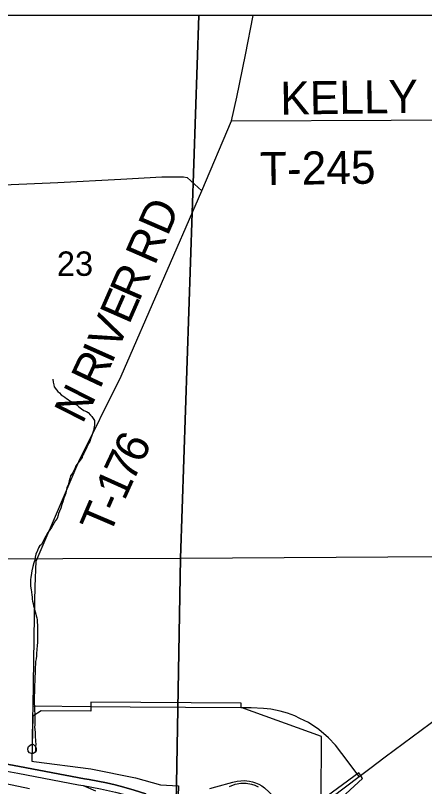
# Model space of a CAD drawing. Extents: x -8.5 to 18.7, y -20.3 to 7.
# Drawn here: x -2.768 to -1.362, y 4.29 to 6.938 of the extents above; entities that cross this region are included whole.
import ezdxf

# ---------------------------------------------------------------- set-up
doc = ezdxf.new("R2010")
doc.units = 0
for name, color, linetype in [('Default', 7, 'Continuous'), ('GM_X_City_Street', 7, 'Continuous'), ('GM_X_Corporation', 7, 'Continuous'), ('GM_X_Interchange_Ramps', 7, 'Continuous'), ('GM_X_Minor_River', 7, 'Continuous'), ('GM_X_Section', 7, 'Continuous'), ('GM_X_Section_Text', 7, 'Continuous'), ('GM_X_State_Route', 7, 'Continuous'), ('GM_X_Township_Road', 7, 'Continuous'), ('GM_X_Township_Road_Text', 7, 'Continuous'), ('GM_X_US_Route', 7, 'Continuous'), ('SH_Cut_Line', 7, 'Continuous')]:
    doc.layers.add(name, color=color, linetype=linetype)

msp = doc.modelspace()

# ---------------------------------------------------------------- linework, layer by layer
at = {"layer": 'Default'}
msp.add_lwpolyline([(-3.0114, 5.0714), (-2.2011, 5.074), (-2.1387, 6.938), (-3.0796, 6.938)], dxfattribs=at)
msp.add_lwpolyline([(-0.1988, 6.938), (-2.1387, 6.938), (-2.2011, 5.074), (-0.2415, 5.0861)], close=True, dxfattribs=at)
at = {"layer": 'GM_X_City_Street'}
for points in [[(-1.9484, 3.9747), (-1.5754, 4.3178), (-1.5825, 4.329), (-1.5882, 4.3371), (-1.7175, 4.2414), (-1.7163, 4.462), (-1.9932, 4.561), (-1.9925, 4.5756), (-2.5089, 4.5796), (-2.5097, 4.5648), (-2.5097, 4.5484), (-2.6796, 4.5501), (-2.7088, 4.5316), (-2.7117, 4.3765), (-2.7049, 4.3756), (-2.5096, 4.3502), (-2.3562, 4.3194), (-2.2694, 4.2958), (-2.2079, 4.2918), (-2.2137, 4.1138)], [(-2.7206, 4.2815), (-3.5022, 4.4472), (-3.5552, 4.4573), (-3.6617, 4.2047)]]:
    msp.add_lwpolyline(points, dxfattribs=at)
at = {"layer": 'GM_X_Corporation'}
msp.add_lwpolyline([(-0.1911, 6.938), (-8.4587, 6.938), (-8.4587, 1.1732)], dxfattribs=at)
at = {"layer": 'GM_X_Interchange_Ramps'}
msp.add_lwpolyline([(-2.0322, 4.2895), (-2.0133, 4.2976), (-1.9941, 4.301), (-1.9751, 4.3014), (-1.957, 4.2981), (-1.9458, 4.2942), (-1.9341, 4.289)], dxfattribs=at)
at = {"layer": 'GM_X_Minor_River'}
for points in [[(-2.6404, 5.6887), (-2.6391, 5.678), (-2.637, 5.6689), (-2.6349, 5.662), (-2.6275, 5.6527), (-2.6224, 5.6466), (-2.6164, 5.6419), (-2.6112, 5.635), (-2.6053, 5.631), (-2.5985, 5.6264), (-2.5933, 5.6225), (-2.5873, 5.6193), (-2.5814, 5.6146), (-2.5724, 5.6092), (-2.5664, 5.6052), (-2.556, 5.599), (-2.55, 5.5935), (-2.5411, 5.5873), (-2.5329, 5.5811), (-2.5246, 5.5778), (-2.5186, 5.5739), (-2.5105, 5.5654), (-2.5053, 5.5608), (-2.4965, 5.5469), (-2.4968, 5.531), (-2.4993, 5.5197), (-2.5002, 5.5121), (-2.5034, 5.5023), (-2.5075, 5.4918), (-2.5107, 5.4827), (-2.5131, 5.4752), (-2.517, 5.4677), (-2.5226, 5.4557), (-2.5289, 5.4421), (-2.5336, 5.4339), (-2.5376, 5.4264), (-2.5392, 5.4203), (-2.5532, 5.4016), (-2.5603, 5.3912), (-2.5634, 5.3844), (-2.5714, 5.3671), (-2.5792, 5.3566), (-2.5816, 5.3476), (-2.5841, 5.34), (-2.5865, 5.331), (-2.5874, 5.3257), (-2.5921, 5.3152), (-2.5939, 5.3053), (-2.5955, 5.2978), (-2.602, 5.2797), (-2.6044, 5.2714), (-2.6092, 5.2578), (-2.6125, 5.2458), (-2.6173, 5.2352), (-2.6205, 5.227), (-2.6221, 5.2217), (-2.6254, 5.2104), (-2.6308, 5.2029), (-2.6449, 5.1789), (-2.652, 5.1684), (-2.6567, 5.1617), (-2.67, 5.1392), (-2.6755, 5.1279), (-2.6787, 5.1211), (-2.6856, 5.1152), (-2.6888, 5.1092), (-2.692, 5.1002), (-2.6983, 5.0874), (-2.7001, 5.0776), (-2.701, 5.0707), (-2.705, 5.0579), (-2.709, 5.0459), (-2.7116, 5.0307), (-2.7133, 5.0224), (-2.7159, 5.0081), (-2.7168, 5.0005), (-2.7165, 4.9785), (-2.7151, 4.9709), (-2.7145, 4.9656), (-2.7131, 4.9587), (-2.7119, 4.9465), (-2.7112, 4.9412), (-2.7106, 4.9336), (-2.7093, 4.926), (-2.7079, 4.9184), (-2.7065, 4.9108), (-2.7044, 4.9031), (-2.7016, 4.8947), (-2.7002, 4.8894), (-2.6988, 4.8818), (-2.6974, 4.8764), (-2.6953, 4.8688), (-2.6939, 4.8627), (-2.6933, 4.8544), (-2.6928, 4.8437), (-2.6922, 4.8354), (-2.6926, 4.8187), (-2.692, 4.8081), (-2.6922, 4.802), (-2.6925, 4.7853), (-2.6935, 4.7732)], [(-2.6935, 4.7732), (-2.6945, 4.7618), (-2.6964, 4.7452), (-2.6965, 4.7391), (-2.6975, 4.7285), (-2.6992, 4.7194), (-2.6993, 4.7126), (-2.7004, 4.6967), (-2.7006, 4.6846), (-2.7019, 4.6611), (-2.7021, 4.6489), (-2.7023, 4.6406), (-2.7034, 4.6231), (-2.7041, 4.5921), (-2.7037, 4.5761), (-2.7024, 4.5639), (-2.7027, 4.5511), (-2.7022, 4.5389), (-2.7017, 4.526), (-2.7022, 4.5017), (-2.7023, 4.4941), (-2.7018, 4.4858), (-2.7005, 4.4751), (-2.7006, 4.4683), (-2.7001, 4.4577), (-2.6994, 4.4516), (-2.6996, 4.4433), (-2.6982, 4.4364), (-2.6992, 4.425), (-2.6995, 4.4114)]]:
    msp.add_lwpolyline(points, dxfattribs=at)
at = {"layer": 'GM_X_Section'}
msp.add_lwpolyline([(-0.2415, 5.0861), (-0.2425, 5.0482), (-0.2637, 3.0843), (-2.2369, 3.07), (-2.2011, 5.074)], close=True, dxfattribs=at)
msp.add_lwpolyline([(-3.0114, 5.0714), (-2.2011, 5.074), (-2.2369, 3.07)], dxfattribs=at)
at = {"layer": 'GM_X_State_Route'}
for points in [[(-2.5151, 4.3134), (-2.5309, 4.3165), (-2.7546, 4.3585), (-3.3528, 4.4711), (-3.4568, 4.4899), (-3.5327, 4.5028), (-3.6527, 4.523), (-3.7428, 4.5391), (-3.8177, 4.5532), (-4.0136, 4.5906), (-4.1567, 4.6172), (-4.2822, 4.6413)], [(-2.3204, 4.2644), (-2.3602, 4.2777), (-2.3957, 4.288), (-2.426, 4.2958), (-2.456, 4.3019), (-2.5151, 4.3134)]]:
    msp.add_lwpolyline(points, dxfattribs=at)
at = {"layer": 'GM_X_Township_Road'}
for p in [(-2.7084, 4.524), (-2.5095, 4.5637)]:
    msp.add_line(p, (-2.7079, 4.5652), dxfattribs=at)
for points in [[(-2.0262, 6.5761), (-2.0075, 6.6572), (-1.9773, 6.803), (-1.9515, 6.938)], [(-2.7079, 4.5652), (-2.7033, 4.8748), (-2.7001, 4.9771), (-2.6973, 5.0638), (-2.6034, 5.2826), (-2.5506, 5.4057), (-2.4054, 5.6996), (-2.1284, 6.3359), (-2.0262, 6.5761)], [(-2.0262, 6.5761), (-1.4769, 6.5781), (-1.1627, 6.5811), (-0.8519, 6.5806), (-0.7429, 6.5791), (-0.6452, 6.5686), (-0.5506, 6.5616), (-0.3569, 6.5587), (-0.198, 6.5557)], [(-2.9656, 6.4716), (-2.9618, 6.4121), (-2.9561, 6.3892), (-2.9442, 6.37), (-2.9385, 6.3603), (-2.9282, 6.3546), (-2.9178, 6.352), (-2.6225, 6.3637), (-2.4066, 6.3758)], [(-2.4066, 6.3758), (-2.2654, 6.3837), (-2.1908, 6.3834), (-2.1787, 6.3816), (-2.1284, 6.3359)], [(-1.9937, 4.5599), (-2.3746, 4.5627), (-2.5095, 4.5637)], [(-1.5877, 4.3237), (-1.6473, 4.4032), (-1.669, 4.4313), (-1.6921, 4.4571), (-1.7255, 4.4852), (-1.7613, 4.5096), (-1.7906, 4.5239), (-1.8084, 4.5322), (-1.8332, 4.5413), (-1.8586, 4.5485), (-1.8903, 4.5553), (-1.9156, 4.558), (-1.958, 4.5597), (-1.9937, 4.5599)], [(-2.7096, 4.4439), (-2.7093, 4.4666), (-2.7087, 4.5096), (-2.7084, 4.524)], [(-2.7077, 4.4037), (-2.7137, 4.4028), (-2.7204, 4.4053), (-2.725, 4.411), (-2.7259, 4.4189), (-2.7236, 4.4268), (-2.719, 4.4307), (-2.7143, 4.4337), (-2.7098, 4.4356), (-2.7096, 4.4439)], [(-2.7071, 4.4348), (-2.7049, 4.4327), (-2.6993, 4.4268), (-2.6968, 4.4201), (-2.6966, 4.4124), (-2.7011, 4.4076), (-2.7057, 4.404), (-2.7077, 4.4037)]]:
    msp.add_lwpolyline(points, dxfattribs=at)
at = {"layer": 'GM_X_US_Route'}
for p, q in [((-1.5828, 4.3274), (-1.55, 4.352)), ((-2.5512, 4.296), (-2.5358, 4.2931)), ((-2.5358, 4.2931), (-2.4937, 4.2749))]:
    msp.add_line(p, q, dxfattribs=at)
for points in [[(-1.55, 4.352), (-1.4976, 4.3914), (-1.2819, 4.5525), (-1.1208, 4.6703), (-0.8982, 4.8336), (-0.4037, 5.1994), (-0.2159, 5.3376)], [(-4.2822, 4.6413), (-4.1567, 4.6172), (-4.0136, 4.5906), (-3.8177, 4.5532), (-3.7428, 4.5391), (-3.6527, 4.523), (-3.5327, 4.5028), (-3.4568, 4.4899), (-3.3528, 4.4711), (-2.7546, 4.3585), (-2.5309, 4.3165), (-2.5151, 4.3134)], [(-2.8243, 4.3473), (-2.7604, 4.3352), (-2.5512, 4.296)], [(-2.0248, 3.9963), (-2.0024, 4.0127), (-1.9829, 4.0273), (-1.8018, 4.1629), (-1.7924, 4.1695), (-1.6809, 4.2532), (-1.5877, 4.3237), (-1.5828, 4.3274)], [(-2.5358, 4.2931), (-2.4759, 4.2815), (-2.4241, 4.2705), (-2.3938, 4.2628), (-2.3634, 4.2538), (-2.3325, 4.2434), (-2.3061, 4.233), (-2.2827, 4.2231), (-2.2595, 4.2118), (-2.2577, 4.2108)], [(-2.5151, 4.3134), (-2.456, 4.3019), (-2.426, 4.2958), (-2.3957, 4.288), (-2.3602, 4.2777), (-2.3204, 4.2644)], [(-2.1004, 4.2833), (-2.0794, 4.2891), (-2.0212, 4.305), (-2.0067, 4.308), (-1.9938, 4.3098), (-1.9829, 4.3099), (-1.9737, 4.3096), (-1.9635, 4.3084), (-1.9532, 4.3062), (-1.9431, 4.3027), (-1.9324, 4.2981), (-1.9222, 4.2919), (-1.9125, 4.2847), (-1.8806, 4.2557), (-1.8025, 4.1831), (-1.7924, 4.1695)]]:
    msp.add_lwpolyline(points, dxfattribs=at)
at = {"layer": 'SH_Cut_Line'}
msp.add_lwpolyline([(18.7413, 6.938), (-8.4587, 6.938), (-8.4587, -10.6981)], dxfattribs=at)

# ---------------------------------------------------------------- texts
at = {"layer": 'GM_X_Section_Text'}
msp.add_text('23', height=0.08371, rotation=0, dxfattribs=at).set_placement((-2.626, 6.0436))
at = {"layer": 'GM_X_Township_Road_Text'}
for s, height, rotation, p in [('KELLY', 0.11364, 0.839, (-1.8575, 6.5968)), ('T-245', 0.11364, 0.8421, (-1.9273, 6.3546)), ('RD', 0.11364, 66.5419, (-2.2895, 6.0763)), ('R', 0.1136, 66.3371, (-2.3439, 5.9513)), ('E', 0.1136, 66.3402, (-2.378, 5.8735)), ('V', 0.1136, 66.3102, (-2.4182, 5.7819)), ('I', 0.1136, 65.9312, (-2.4376, 5.7385)), ('R', 0.1136, 64.7336, (-2.4785, 5.6518)), ('N', 0.1136, 63.0027, (-2.5383, 5.5321)), ('6', 0.1136, 63.7887, (-2.3354, 5.3945)), ('7', 0.1136, 64.6546, (-2.3651, 5.3316)), ('1', 0.1136, 65.7094, (-2.3937, 5.2683)), ('T', 0.1136, 66.8869, (-2.4454, 5.1479)), ('-', 0.1136, 66.5503, (-2.4121, 5.2259))]:
    msp.add_text(s, height=height, rotation=rotation, dxfattribs=at).set_placement(p)

doc.saveas('drawing.dxf')
